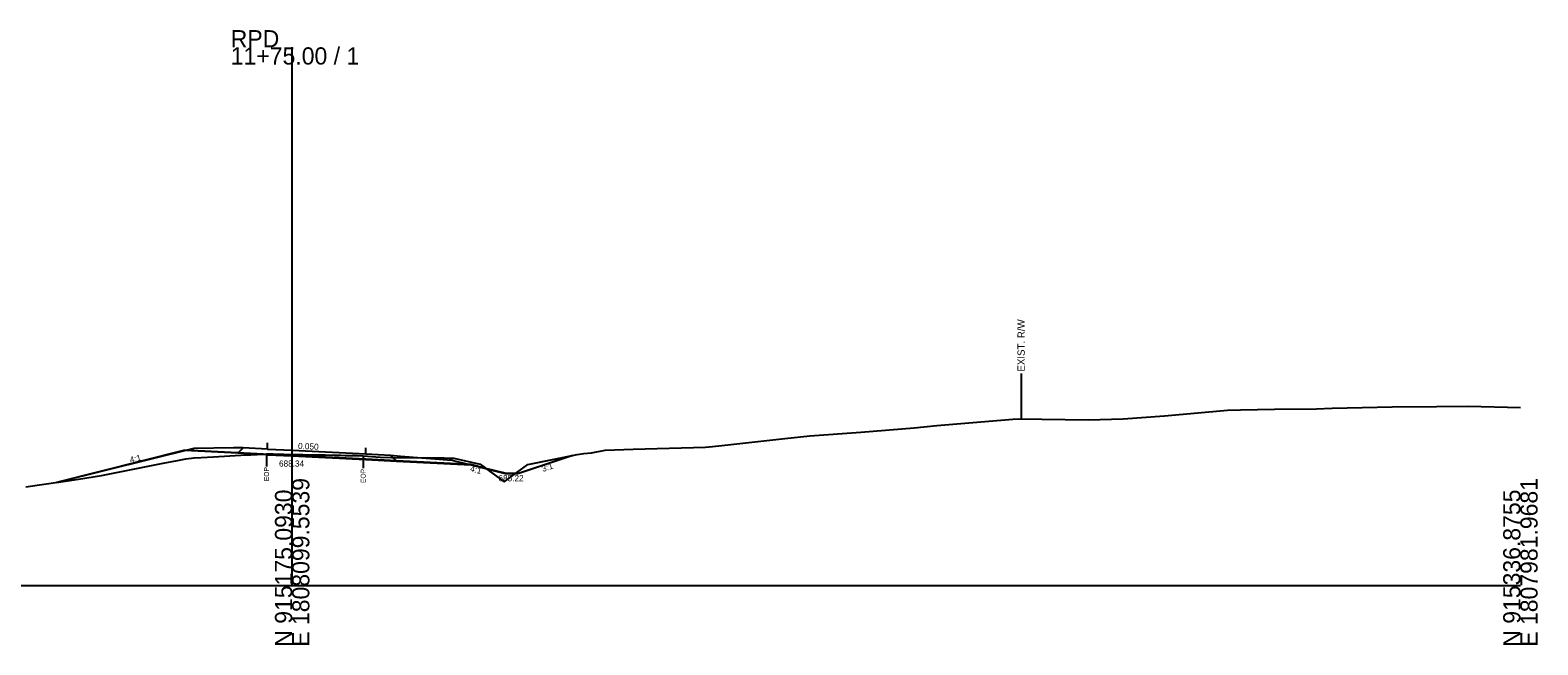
# Model space of a CAD drawing. Extents: x -26 to 403, y -10 to 8517.
# Drawn here: x 157.3 to 402.8, y 3490.3 to 3590.4 of the extents above; entities that cross this region are included whole.
import ezdxf

# ---------------------------------------------------------------- set-up
doc = ezdxf.new("R2010")
doc.units = 0
for name, color, linetype in [('Exist Cross Section Cell', 7, 'Continuous'), ('Exist XS Center Line Elevation Label', 7, 'Continuous'), ('Exist XS Ground Line', 7, 'Continuous'), ('Old_Level_10', 7, 'Continuous'), ('Prop XS Ditch Slope Text', 7, 'Continuous'), ('Prop XS Ditch Standard Text', 7, 'Continuous'), ('Prop XS Earthwork Shape', 7, 'Continuous'), ('Prop XS EOT Tick Mark', 7, 'Continuous'), ('Prop XS Finish Grade', 7, 'Continuous'), ('Prop XS Finish Grade Earthwork', 7, 'Continuous'), ('Prop XS Finish Grade Paved Shoulder', 7, 'Continuous'), ('Prop XS Finish Grade Pavement', 7, 'Continuous'), ('Prop XS Hydro Fill Slope Data', 7, 'Continuous'), ('Prop XS Pvmt Edge Slope', 7, 'Continuous'), ('Prop XS SE Text', 7, 'Continuous'), ('Prop XS Side Slope Text', 7, 'Continuous'), ('Prop XS Subgrade Earthwork', 7, 'Continuous')]:
    doc.layers.add(name, color=color, linetype=linetype)

msp = doc.modelspace()

# ---------------------------------------------------------------- linework, layer by layer
at = {"layer": 'Exist Cross Section Cell'}
for p, q in [((200, 3500), (200, 3587.64)), ((0, 3500), (200, 3500)), ((200, 3500), (400, 3500))]:
    msp.add_line(p, q, dxfattribs=at)
at = {"layer": 'Exist XS Ground Line'}
msp.add_lwpolyline([(156.62, 3516.05), (165.22, 3517.28), (168.98, 3517.91), (178.97, 3519.9), (181.34, 3520.36), (182.71, 3520.59), (184.04, 3520.78), (185.19, 3520.84), (187.21, 3520.96), (192.52, 3521.25), (193.29, 3521.27), (194.33, 3521.29), (195.17, 3521.36), (195.81, 3521.42), (196.91, 3521.4), (198.64, 3521.37), (200, 3521.34), (201.12, 3521.32), (201.73, 3521.3), (203.77, 3521.27), (204.49, 3521.26), (205.06, 3521.25), (205.39, 3521.24), (206.84, 3521.21), (207.91, 3521.19), (208.64, 3521.17), (209.64, 3521.15), (210.75, 3521.13), (211.57, 3521.12), (214.31, 3520.9), (216.16, 3520.82), (222.26, 3520.77), (224.08, 3520.75), (224.77, 3520.75), (225.51, 3520.74), (226.34, 3520.73), (230.62, 3519.76), (234.51, 3516.85), (238.38, 3519.71), (246.43, 3521.29), (247.49, 3521.46), (248.74, 3521.59), (250.97, 3522.02), (255.52, 3522.19), (267.28, 3522.5), (267.88, 3522.58), (269.48, 3522.75), (280.24, 3523.92), (284.29, 3524.37), (292.6, 3524.98), (301.29, 3525.65), (304.96, 3526.03), (314.73, 3526.85), (317.33, 3527.07), (318.3, 3527.12), (329.69, 3526.97), (335.31, 3527.14), (342.05, 3527.6), (352.32, 3528.51), (354.41, 3528.59), (359.98, 3528.69), (366.78, 3528.74), (369.33, 3528.87), (379.14, 3529.09), (386.34, 3529.15), (391.5, 3529.21), (400, 3528.96)], dxfattribs=at)
at = {"layer": 'Old_Level_10'}
for p, q in [((318.7, 3534.52), (318.7, 3527.11)), ((195.81, 3521.42), (195.81, 3519.37)), ((211.57, 3521.12), (211.57, 3519.07))]:
    msp.add_line(p, q, dxfattribs=at)
at = {"layer": 'Prop XS Earthwork Shape'}
for points in [[(182.54, 3522), (161.62, 3516.77), (165.22, 3517.28), (168.98, 3517.91), (178.97, 3519.9), (181.34, 3520.36), (182.71, 3520.59), (184.04, 3520.78), (185.19, 3520.84), (187.21, 3520.96), (192.52, 3521.25), (193.29, 3521.27), (194.33, 3521.29), (195.17, 3521.36), (195.27, 3521.37), (191.13, 3521.57)], [(195.27, 3521.37), (195.81, 3521.42), (196.91, 3521.4), (198.64, 3521.37), (200, 3521.34), (201.12, 3521.32), (201.73, 3521.3), (203.77, 3521.27), (204.49, 3521.26), (205.06, 3521.25), (205.39, 3521.24), (206.84, 3521.21), (207.91, 3521.19), (208.64, 3521.17), (209.64, 3521.15), (210.75, 3521.13), (211.57, 3521.12), (214.31, 3520.9), (216.16, 3520.82), (222.26, 3520.77), (224.08, 3520.75), (224.77, 3520.75), (225.51, 3520.74), (226.34, 3520.73), (230.62, 3519.76), (231.56, 3519.06), (229.09, 3519.68), (216.97, 3520.28), (211.98, 3520.53), (199.98, 3521.13), (195.98, 3521.33)], [(238.38, 3519.71), (245.7, 3521.14), (236.92, 3518.22), (236.37, 3518.22)], [(234.51, 3516.85), (236.37, 3518.22), (234.92, 3518.22), (231.56, 3519.06)]]:
    msp.add_lwpolyline(points, close=True, dxfattribs=at)
at = {"layer": 'Prop XS EOT Tick Mark'}
for p, q in [((196, 3522.19), (196, 3523.19)), ((212, 3521.4), (212, 3522.4))]:
    msp.add_line(p, q, dxfattribs=at)
at = {"layer": 'Prop XS Finish Grade'}
for p, q in [((182.54, 3521.94), (184, 3522.31)), ((190.43, 3522.38), (184, 3522.31)), ((192, 3522.39), (190.43, 3522.38)), ((216, 3521.2), (217.62, 3521.07)), ((217.62, 3521.07), (226, 3520.4)), ((226, 3520.4), (229.09, 3519.62))]:
    msp.add_line(p, q, dxfattribs=at)
at = {"layer": 'Prop XS Finish Grade Earthwork'}
for p, q in [((182.54, 3521.94), (162.12, 3516.84)), ((236.71, 3518.22), (245.18, 3521.04)), ((229.09, 3519.62), (234.71, 3518.22)), ((234.71, 3518.22), (236.71, 3518.22))]:
    msp.add_line(p, q, dxfattribs=at)
at = {"layer": 'Prop XS Finish Grade Paved Shoulder'}
for p, q in [((196, 3522.19), (192, 3522.39)), ((212, 3521.4), (216, 3521.2))]:
    msp.add_line(p, q, dxfattribs=at)
at = {"layer": 'Prop XS Finish Grade Pavement'}
for p, q in [((196, 3522.19), (200, 3522)), ((200, 3522), (212, 3521.4))]:
    msp.add_line(p, q, dxfattribs=at)
at = {"layer": 'Prop XS Hydro Fill Slope Data'}
msp.add_line((184, 3522.31), (162.12, 3516.84), dxfattribs=at)
at = {"layer": 'Prop XS Pvmt Edge Slope'}
for p, q in [((192, 3522.39), (191.13, 3521.52)), ((216, 3521.2), (216.97, 3520.23))]:
    msp.add_line(p, q, dxfattribs=at)
at = {"layer": 'Prop XS Subgrade Earthwork'}
for p, q in [((191.13, 3521.52), (182.54, 3521.94)), ((195.98, 3521.28), (191.13, 3521.52)), ((195.98, 3521.28), (199.98, 3521.08)), ((199.98, 3521.08), (211.98, 3520.48)), ((211.98, 3520.48), (216.97, 3520.23)), ((216.97, 3520.23), (229.09, 3519.62))]:
    msp.add_line(p, q, dxfattribs=at)

# ---------------------------------------------------------------- texts
at = {"layer": 'Exist Cross Section Cell'}
for s, p in [('RPD', (190, 3587.64)), ('11+75.00 / 1', (190, 3584.84))]:
    msp.add_text(s, height=2.8, dxfattribs=at).set_placement(p)
for s, p in [('E 1808099.5539', (202.8, 3490)), ('E 1807981.9681', (402.8, 3490)), ('N 915175.0930', (200, 3490)), ('N 915336.8755', (400, 3490))]:
    msp.add_text(s, height=2.8, rotation=90, dxfattribs=at).set_placement(p)
at = {"layer": 'Exist XS Center Line Elevation Label'}
msp.add_text('688.34', height=1, dxfattribs=at).set_placement((197.86, 3519.34))
at = {"layer": 'Old_Level_10'}
for s, height, rotation, p in [('EXIST. R/W', 1.181, 90, (319.29, 3534.82)), ('EOP', 0.787, 90, (196.21, 3516.97)), ('EOP', 0.787, 90, (211.96, 3516.67)), ('3:1', 1, 18.4349, (240.83, 3518.46))]:
    msp.add_text(s, height=height, rotation=rotation, dxfattribs=at).set_placement(p)
at = {"layer": 'Prop XS Ditch Slope Text'}
msp.add_text('4:1', height=1, rotation=345.9638, dxfattribs=at).set_placement((228.9, 3518.57))
at = {"layer": 'Prop XS Ditch Standard Text'}
msp.add_text('685.22', height=1, dxfattribs=at).set_placement((233.6, 3516.96))
at = {"layer": 'Prop XS SE Text'}
msp.add_text('0.050', height=1, rotation=357.1373, dxfattribs=at).set_placement((200.94, 3522.23))
at = {"layer": 'Prop XS Side Slope Text'}
msp.add_text('4:1', height=1, rotation=14.0362, dxfattribs=at).set_placement((173.69, 3519.92))

doc.saveas('drawing.dxf')
